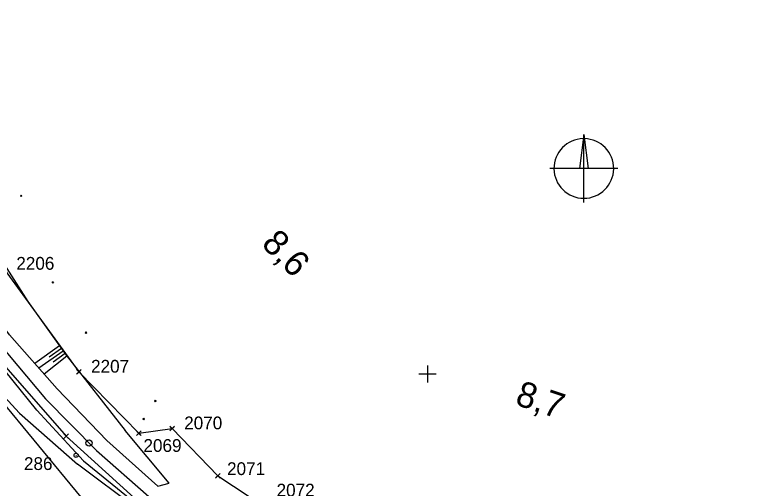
# Model space of a CAD drawing. Extents: x -866402 to -860377, y -1041908 to -1038598.
# Drawn here: x -863296.8 to -863121.8, y -1039926.8 to -1039815.7 of the extents above; entities that cross this region are included whole.
import ezdxf

# ---------------------------------------------------------------- set-up
doc = ezdxf.new("R2010")
doc.units = 0
for name, color, linetype in [('PS 02 trasa', 7, 'Continuous'), ('SZDC', 7, 'Continuous'), ('Vrstva 1', 7, 'Continuous'), ('Vrstva 2', 7, 'Continuous'), ('Vrstva 48', 7, 'Continuous'), ('Vrstva 49', 7, 'Continuous'), ('Vrstva 5', 7, 'Continuous'), ('Vrstva 60', 7, 'Continuous'), ('Vrstva 7', 7, 'Continuous')]:
    doc.layers.add(name, color=color, linetype=linetype)

msp = doc.modelspace()

# ---------------------------------------------------------------- linework, layer by layer
at = {"layer": 'PS 02 trasa'}
msp.add_lwpolyline([(-863478.37, -1039730.49), (-863454.97, -1039738.4), (-863432.43, -1039748.79), (-863411.14, -1039761.69), (-863391.7, -1039776.76), (-863373.86, -1039793.88), (-863357.56, -1039813.36), (-863343.38, -1039833.77), (-863329.62, -1039854.78), (-863315.73, -1039875.65), (-863301.15, -1039895.87), (-863284.71, -1039914.61), (-863266.26, -1039931.32), (-863245.45, -1039946.31)], dxfattribs=at)
at = {"layer": 'SZDC'}
for points in [[(-863748.01, -1039848.49), (-863725.76, -1039812), (-863710.18, -1039790.69), (-863681.49, -1039761.05), (-863641.52, -1039733.19), (-863638.92, -1039731.44), (-863624.3, -1039721.59), (-863586.13, -1039705.52), (-863566.28, -1039696.72), (-863563.11, -1039695.31), (-863540.66, -1039696.99), (-863537.82, -1039697.2), (-863510.6, -1039699.81), (-863460.34, -1039717.62), (-863450.7, -1039722.54), (-863407.1, -1039744.81), (-863377.64, -1039762.09), (-863356.59, -1039780.85), (-863352.89, -1039784.15), (-863325.61, -1039827), (-863299.27, -1039875.39), (-863281.74, -1039899.54), (-863267.72, -1039913.93)], [(-863110.71, -1039983.7), (-863135.81, -1039985.12), (-863165.72, -1039981.71), (-863206.44, -1039970.59), (-863218.01, -1039993.65), (-863250.78, -1039975.29), (-863249.44, -1039956.85), (-863260.7, -1039944.56), (-863266.56, -1039936.51), (-863268.95, -1039933.23), (-863273.75, -1039934.47), (-863278.33, -1039932.46), (-863281.22, -1039928.96), (-863320.99, -1039880.75), (-863334.07, -1039862.91), (-863355.91, -1039833.12), (-863382.19, -1039801.42), (-863404.46, -1039782.26), (-863434.71, -1039754.45), (-863437.97, -1039751.45), (-863444.08, -1039745.83), (-863485.07, -1039745.76)], [(-863267.72, -1039913.93), (-863259.9, -1039912.84), (-863249.16, -1039923.89), (-863237.88, -1039931.33), (-863182.32, -1039940.79), (-863145.82, -1039947.55), (-863099.72, -1039942.9), (-863062.77, -1039937.98), (-863020.67, -1039917.62), (-862999.7, -1039916.39), (-863054.66, -1039950.34), (-863084.19, -1039960.59), (-863119.01, -1039963.27), (-863165.47, -1039960.73), (-863203.02, -1039951.02), (-863218.8, -1039944.91)]]:
    msp.add_lwpolyline(points, dxfattribs=at)
at = {"layer": 'Vrstva 1'}
msp.add_lwpolyline([(-863324.65, -1039857.82), (-863320.3, -1039864.52), (-863310.83, -1039878.68), (-863300.59, -1039892.76), (-863289.55, -1039905.88), (-863277.61, -1039918.01), (-863265.38, -1039928.74), (-863252.72, -1039938.38), (-863238.84, -1039947.37), (-863234.66, -1039949.79), (-863219.75, -1039957.46), (-863203.97, -1039964.13), (-863187.71, -1039969.56), (-863171.45, -1039973.63), (-863155.73, -1039976.37), (-863139.24, -1039978), (-863122.49, -1039978.38), (-863105.35, -1039977.46)], dxfattribs=at)
at = {"layer": 'Vrstva 2'}
for p, q in [((-863163.34, -1039843.77), (-863164.34, -1039851.77)), ((-863163.34, -1039859.77), (-863163.34, -1039843.77)), ((-863155.34, -1039851.77), (-863171.34, -1039851.77))]:
    msp.add_line(p, q, dxfattribs=at)
msp.add_lwpolyline([(-863163.34, -1039843.77), (-863162.34, -1039851.77), (-863163.34, -1039851.77)], close=True, dxfattribs=at)
msp.add_arc((-863163.34, -1039851.77), 7, 91.0243, 88.9757, dxfattribs=at)
at = {"layer": 'Vrstva 48'}
for p, q in [((-863286.3, -1039893.4), (-863292.11, -1039897.56)), ((-863285.43, -1039894.62), (-863291.11, -1039898.68)), ((-863285.87, -1039894.01), (-863288.74, -1039896.07)), ((-863284.55, -1039895.83), (-863289.91, -1039900.03)), ((-863284.99, -1039895.23), (-863287.8, -1039897.24))]:
    msp.add_line(p, q, dxfattribs=at)
at = {"layer": 'Vrstva 49'}
for p, q in [((-863295.46, -1039858.04), (-863295.11, -1039858.39)), ((-863295.46, -1039858.39), (-863295.11, -1039858.04)), ((-863288.06, -1039878.34), (-863287.71, -1039878.69)), ((-863288.06, -1039878.69), (-863287.71, -1039878.34)), ((-863280.26, -1039890.13), (-863279.9, -1039890.49)), ((-863280.26, -1039890.49), (-863279.9, -1039890.13)), ((-863264, -1039906.15), (-863263.65, -1039906.5)), ((-863264, -1039906.5), (-863263.65, -1039906.15)), ((-863266.75, -1039910.35), (-863266.4, -1039910.71)), ((-863266.75, -1039910.71), (-863266.4, -1039910.35)), ((-863260.6, -1039925.66), (-863270.88, -1039913.28)), ((-863263.24, -1039926.35), (-863275.22, -1039915.63)), ((-863263.24, -1039926.35), (-863260.6, -1039925.66))]:
    msp.add_line(p, q, dxfattribs=at)
for points in [[(-863332.04, -1039819.2), (-863321.61, -1039838.74), (-863309.39, -1039858.22), (-863304.94, -1039865.55), (-863293.74, -1039883.02), (-863284.75, -1039895.57), (-863270.88, -1039913.28)], [(-863275.22, -1039915.63), (-863286.88, -1039903.46), (-863298.04, -1039890.86), (-863308.36, -1039876.85), (-863318.03, -1039862.94), (-863322.47, -1039856.39), (-863331.6, -1039842.28), (-863340.38, -1039827.26)], [(-863352.21, -1039837.58), (-863341.46, -1039852.43), (-863330.12, -1039866.64), (-863317.85, -1039883.45), (-863307.31, -1039896.58), (-863295.72, -1039909.19), (-863282.09, -1039921.22)], [(-863280.66, -1039920.38), (-863291.59, -1039908.5), (-863302.79, -1039894.71), (-863313.57, -1039880.21), (-863322.59, -1039866.37), (-863326.79, -1039859.68), (-863336.66, -1039845.37)], [(-863280.66, -1039920.38), (-863267.26, -1039931.38), (-863266.22, -1039932.36)], [(-863266.22, -1039932.36), (-863268.11, -1039931.69), (-863282.09, -1039921.22)]]:
    msp.add_lwpolyline(points, dxfattribs=at)
at = {"layer": 'Vrstva 5'}
for p, q in [((-863200, -1039898), (-863200, -1039902)), ((-863202, -1039900), (-863198, -1039900))]:
    msp.add_line(p, q, dxfattribs=at)
at = {"layer": 'Vrstva 60'}
for p, q in [((-863281.29, -1039899.99), (-863282.29, -1039898.99)), ((-863281.29, -1039899.09), (-863282.29, -1039900.09)), ((-863282.19, -1039899.99), (-863281.19, -1039898.99)), ((-863282.19, -1039899.09), (-863281.19, -1039900.09)), ((-863281.74, -1039899.54), (-863281.74, -1039899.54)), ((-863259.45, -1039913.29), (-863260.45, -1039912.29)), ((-863259.45, -1039912.39), (-863260.45, -1039913.39)), ((-863260.35, -1039913.29), (-863259.35, -1039912.29)), ((-863260.35, -1039912.39), (-863259.35, -1039913.39)), ((-863284.27, -1039915.06), (-863285.27, -1039914.06)), ((-863285.17, -1039915.06), (-863284.17, -1039914.06)), ((-863267.27, -1039914.38), (-863268.27, -1039913.38)), ((-863267.27, -1039913.48), (-863268.27, -1039914.48)), ((-863268.17, -1039914.38), (-863267.17, -1039913.38)), ((-863268.17, -1039913.48), (-863267.17, -1039914.48)), ((-863267.72, -1039913.93), (-863267.72, -1039913.93)), ((-863259.9, -1039912.84), (-863259.9, -1039912.84)), ((-863284.27, -1039914.16), (-863285.27, -1039915.16)), ((-863285.17, -1039914.16), (-863284.17, -1039915.16)), ((-863284.71, -1039914.61), (-863284.71, -1039914.61)), ((-863248.71, -1039924.34), (-863249.71, -1039923.34)), ((-863248.71, -1039923.44), (-863249.71, -1039924.44)), ((-863249.61, -1039924.34), (-863248.61, -1039923.34)), ((-863249.61, -1039923.44), (-863248.61, -1039924.44)), ((-863249.16, -1039923.89), (-863249.16, -1039923.89))]:
    msp.add_line(p, q, dxfattribs=at)
at = {"layer": 'Vrstva 7'}
msp.add_line((-863282.45, -1039919.11), (-863282.35, -1039919.11), dxfattribs=at)
for centre, radius in [((-863279.38, -1039916.2), 0.75), ((-863282.4, -1039919.11), 0.5)]:
    msp.add_circle(centre, radius, dxfattribs=at)

# ---------------------------------------------------------------- texts
at = {"layer": 'Vrstva 60'}
for s, p in [('2206', (-863296.43, -1039875.54)), ('2207', (-863278.9, -1039899.7)), ('2070', (-863257.06, -1039913)), ('2069', (-863266.61, -1039918.3)), ('286', (-863294.64, -1039922.55)), ('2071', (-863247.01, -1039923.74)), ('2072', (-863235.39, -1039928.78))]:
    msp.add_text(s, height=3, dxfattribs=at).set_placement(p)
at = {"layer": 'Vrstva 7'}
for s, rotation, p in [('8,6', 314.5739, (-863239.18, -1039869.72)), ('8,7', 341.546, (-863179.7, -1039907.12))]:
    msp.add_text(s, height=6, rotation=rotation, dxfattribs=at).set_placement(p)

doc.saveas('drawing.dxf')
